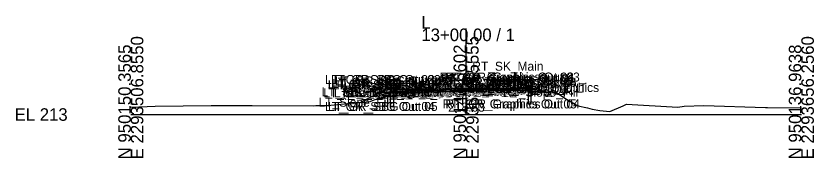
# Model space of a CAD drawing. Extents: x -26 to 7053, y -10 to 7035.
# Drawn here: x -25.7 to 152.8, y 1990.3 to 2022 of the extents above; entities that cross this region are included whole.
import ezdxf

# ---------------------------------------------------------------- set-up
doc = ezdxf.new("R2010")
doc.units = 0
for name, color, linetype in [('Default', 7, 'Continuous'), ('Exist Cross Section Cell', 7, 'Continuous'), ('Exist XS Center Line Elevation Label', 7, 'Continuous'), ('Exist XS Ground Line', 7, 'Continuous'), ('Prop CMT Conc Surface', 7, 'Continuous'), ('Prop CMT Concrete Structures', 7, 'Continuous'), ('Prop CMT Guardrail Graphics', 7, 'Continuous'), ('Prop CMT Guardrail SBG', 7, 'Continuous'), ('Prop CMT Pvmt Course 1', 7, 'Continuous'), ('Prop CMT Pvmt Course 2', 7, 'Continuous'), ('Prop CMT Pvmt Course SBG', 7, 'Continuous'), ('Prop CMT Pvmt Surface', 7, 'Continuous'), ('Prop CMT Pvmt Surface Overlay', 7, 'Continuous'), ('Prop CMT Pvmt Surface Shoulder', 7, 'Continuous'), ('Prop CMT Shld Paved Course 1', 7, 'Continuous'), ('Prop CMT Shld Paved Course 2', 7, 'Continuous'), ('Prop CMT Slope Grass', 7, 'Continuous'), ('Prop CMT Subgrade Earthwork', 7, 'Continuous'), ('Prop XS EOT Tick Mark', 7, 'Continuous'), ('Prop XS SE Text', 7, 'Continuous'), ('Prop XS Side Slope Text', 7, 'Continuous')]:
    doc.layers.add(name, color=color, linetype=linetype)

msp = doc.modelspace()

# ---------------------------------------------------------------- linework, layer by layer
at = {"layer": 'Exist Cross Section Cell'}
for p, q in [((75, 2000), (75, 2019.17)), ((0, 2000), (75, 2000)), ((75, 2000), (150, 2000))]:
    msp.add_line(p, q, dxfattribs=at)
at = {"layer": 'Exist XS Ground Line'}
for p, q in [((63.41, 2004.79), (66.65, 2005.24)), ((66.65, 2005.24), (67.11, 2005.31)), ((67.11, 2005.31), (67.58, 2005.32)), ((67.58, 2005.32), (75.03, 2005.63)), ((75.03, 2005.63), (82.28, 2005.69)), ((82.28, 2005.69), (83.65, 2005.7)), ((83.65, 2005.7), (85.36, 2005.56)), ((85.36, 2005.56), (95.43, 2004.79)), ((54.05, 2003.12), (54.9, 2003.41)), ((54.9, 2003.41), (56.91, 2003.91)), ((56.91, 2003.91), (63.41, 2004.79)), ((95.43, 2004.79), (97.12, 2003.62)), ((97.12, 2003.62), (100, 2001.97)), ((0, 2001.64), (5.42, 2001.85)), ((5.42, 2001.85), (17.98, 2002.01)), ((17.98, 2002.01), (20.9, 2001.99)), ((20.9, 2001.99), (27.15, 2002)), ((27.15, 2002), (40.89, 2001.96)), ((40.89, 2001.96), (41.42, 2002.03)), ((41.42, 2002.03), (43.98, 2002.04)), ((43.98, 2002.04), (50.01, 2002.64)), ((50.01, 2002.64), (53.56, 2002.89)), ((53.56, 2002.89), (54.05, 2003.12)), ((100, 2001.97), (102.17, 2001.49)), ((102.17, 2001.49), (103.24, 2001.19)), ((107.17, 2000.66), (110.15, 2001.96)), ((110.15, 2001.96), (110.87, 2002.28)), ((110.87, 2002.28), (122.35, 2001.67)), ((122.35, 2001.67), (123.79, 2001.84)), ((123.79, 2001.84), (128.22, 2002)), ((128.22, 2002), (141.98, 2001.57)), ((141.98, 2001.57), (142.43, 2001.58)), ((142.43, 2001.58), (150, 2001.51)), ((103.24, 2001.19), (104.94, 2000.92)), ((104.94, 2000.92), (107.17, 2000.66))]:
    msp.add_line(p, q, dxfattribs=at)
at = {"layer": 'Prop CMT Conc Surface'}
msp.add_lwpolyline([(62.03, 2005.51), (59.7, 2005.42), (59.03, 2005.76)], dxfattribs=at)
at = {"layer": 'Prop CMT Concrete Structures'}
for points in [[(62.03, 2005.51), (59.7, 2005.42), (59.03, 2005.76)], [(59.03, 2005.76), (59.03, 2005.09)], [(59.03, 2005.09), (62.03, 2005.09)], [(62.03, 2005.09), (62.03, 2005.51)]]:
    msp.add_lwpolyline(points, dxfattribs=at)
at = {"layer": 'Prop CMT Guardrail Graphics'}
for points in [[(89.55, 2008.36), (88.22, 2008.36), (87.95, 2008.07)], [(87.95, 2008.07), (88.22, 2007.78)], [(88.22, 2007.78), (87.95, 2007.48)], [(87.95, 2007.48), (88.22, 2007.19), (88.89, 2007.19)], [(88.89, 2007.19), (88.89, 2002.36)], [(89.55, 2002.36), (89.55, 2008.36)], [(88.89, 2002.36), (89.55, 2002.36)]]:
    msp.add_lwpolyline(points, dxfattribs=at)
at = {"layer": 'Prop CMT Guardrail SBG'}
for points in [[(58.09, 2001.8), (58.09, 2007.8)], [(58.09, 2007.8), (59.43, 2007.8), (59.7, 2007.5)], [(59.7, 2006.92), (59.43, 2006.63), (58.76, 2006.63)], [(59.7, 2007.5), (59.43, 2007.21)], [(59.43, 2007.21), (59.7, 2006.92)], [(58.76, 2006.63), (58.76, 2001.8)], [(58.76, 2001.8), (58.09, 2001.8)]]:
    msp.add_lwpolyline(points, dxfattribs=at)
at = {"layer": 'Prop CMT Pvmt Course 1'}
for points in [[(75, 2005.77), (65, 2005.57)], [(65, 2005.57), (65, 2005.32)], [(65, 2005.32), (75, 2005.52)], [(75, 2005.77), (85, 2005.97)], [(75, 2005.64), (75, 2005.77)], [(75, 2005.64), (75, 2005.77)], [(85, 2005.72), (75, 2005.52)], [(75, 2005.52), (75, 2005.64), (75, 2005.64)], [(75, 2005.52), (75, 2005.64), (75, 2005.64)], [(85, 2005.97), (85, 2005.72)]]:
    msp.add_lwpolyline(points, dxfattribs=at)
at = {"layer": 'Prop CMT Pvmt Course 2'}
for points in [[(75, 2005.52), (65, 2005.32)], [(65, 2005.32), (65, 2004.98)], [(65, 2004.98), (75, 2005.18)], [(75, 2005.52), (85, 2005.72)], [(75, 2005.18), (75, 2005.52)], [(75, 2005.18), (75, 2005.52)], [(85, 2005.38), (75, 2005.18)], [(85, 2005.72), (85, 2005.38)]]:
    msp.add_lwpolyline(points, dxfattribs=at)
at = {"layer": 'Prop CMT Pvmt Course SBG'}
for points in [[(62.03, 2005.09), (59.03, 2005.09), (58.53, 2005.09), (58.28, 2004.84)], [(62.03, 2004.84), (62.03, 2005.09)], [(58.28, 2004.84), (62.03, 2004.84)]]:
    msp.add_lwpolyline(points, dxfattribs=at)
at = {"layer": 'Prop CMT Pvmt Surface'}
for points in [[(75, 2005.77), (65, 2005.57)], [(75, 2005.77), (85, 2005.97)]]:
    msp.add_lwpolyline(points, dxfattribs=at)
at = {"layer": 'Prop CMT Pvmt Surface Overlay'}
for points in [[(75, 2005.77), (65, 2005.57)], [(75, 2005.77), (85, 2005.97)]]:
    msp.add_lwpolyline(points, dxfattribs=at)
at = {"layer": 'Prop CMT Pvmt Surface Shoulder'}
for points in [[(65, 2005.57), (62.03, 2005.51)], [(85, 2005.97), (87.93, 2006.03)]]:
    msp.add_lwpolyline(points, dxfattribs=at)
at = {"layer": 'Prop CMT Shld Paved Course 1'}
for points in [[(65, 2005.57), (62.03, 2005.51)], [(62.03, 2005.51), (62.03, 2005.26)], [(62.03, 2005.26), (65, 2005.32)], [(65, 2005.32), (65, 2005.57)], [(85, 2005.97), (87.93, 2006.03), (88.18, 2005.78)], [(85, 2005.72), (85, 2005.97)], [(88.18, 2005.78), (85, 2005.72)]]:
    msp.add_lwpolyline(points, dxfattribs=at)
at = {"layer": 'Prop CMT Shld Paved Course 2'}
for points in [[(65, 2005.32), (62.03, 2005.26)], [(62.03, 2005.26), (62.03, 2005.09), (62.03, 2004.93)], [(62.03, 2004.93), (65, 2004.98)], [(65, 2004.98), (65, 2005.32)], [(85, 2005.72), (88.18, 2005.78), (88.68, 2005.79), (89, 2005.46)], [(85, 2005.38), (85, 2005.72)], [(89, 2005.46), (85, 2005.38)]]:
    msp.add_lwpolyline(points, dxfattribs=at)
at = {"layer": 'Prop CMT Slope Grass'}
for points in [[(59.03, 2005.76), (58.28, 2006.14), (51.48, 2002.74)], [(87.93, 2006.03), (87.95, 2006.03)], [(87.95, 2006.03), (90.95, 2005.91)], [(90.95, 2005.91), (92.78, 2004.99)]]:
    msp.add_lwpolyline(points, dxfattribs=at)
at = {"layer": 'Prop CMT Subgrade Earthwork'}
for points in [[(65, 2004.98), (62.03, 2004.93)], [(62.03, 2004.93), (62.03, 2004.84)], [(75, 2005.18), (65, 2004.98)], [(75, 2005.18), (85, 2005.38)], [(85, 2005.38), (89, 2005.46)], [(89, 2005.46), (89.5, 2005.96)], [(62.03, 2004.84), (58.28, 2004.84), (55.68, 2004.84)]]:
    msp.add_lwpolyline(points, dxfattribs=at)
at = {"layer": 'Prop XS EOT Tick Mark'}
for p, q in [((65, 2005.57), (65, 2007.47)), ((85, 2005.97), (85, 2007.87))]:
    msp.add_line(p, q, dxfattribs=at)

# ---------------------------------------------------------------- texts
at = {"layer": 'Default'}
for s, height, p in [('RT_SK_Main', 2, (76.4, 2009.77)), ('LT_GR_SBG Out 03', 2, (43.45, 2006.8)), ('LT_GR_SBG Out 02', 2, (44.78, 2006.8)), ('LT_GR_SBG Out 01', 2, (45.62, 2006.5)), ('RT_GR_Graphics Out 08', 2, (68.8, 2006.48)), ('RT_GR_Graphics Out 02', 2, (69.07, 2007.36)), ('RT_GR_Graphics Out 09', 2, (69.07, 2006.78)), ('RT_GR_Graphics Out 01', 2, (69.37, 2007.07)), ('RT_GR_Graphics Out 03', 2, (70.4, 2007.36)), ('LT_GR_SBG Out 06', 2, (44.07, 2005.63)), ('LT_GR_SBG Out 09', 2, (44.78, 2006.21)), ('LT_GR_SBG Out 07', 2, (44.78, 2005.63)), ('LT_GR_SBG Out 08', 2, (45.05, 2005.92)), ('LT_CG_Top_BOC', 2, (47.31, 2004.76)), ('LT_GS_OS_CTL', 2, (47.65, 2005.14)), ('LT_TM_OEOT', 2, (57.94, 2005.61)), ('RT_GS_OS_GR_Face_Graphics', 2, (65.36, 2005.03)), ('RT_GR_Graphics Out 07', 2, (69.07, 2006.19)), ('PV1_PGL', 2, (69.47, 2004.77)), ('RT_GR_Graphics Out 06', 2, (69.69, 2006.19)), ('RT_Sub_Trench_Out_DLT', 2, (70.02, 2004.96)), ('RT_TM_OEOT', 2, (73.9, 2005.93)), ('RT_PS2_Shelf_Out', 2, (74.61, 2004.79)), ('RT_PV2_OEOT', 2, (75.13, 2004.72)), ('RT_PV1_OEOT', 2, (75.69, 2004.97)), ('RT_PS2_OEOP', 2, (78.37, 2004.78)), ('RT_PS1_OEOP', 2, (78.69, 2005.03)), ('RT_GS_OS_CTL', 2, (80.27, 2004.91)), ('LT_SBG_C1 Shelf Out', 2, (42.67, 2004.09)), ('LT_Sub_OSS_DLT', 2, (43.08, 2003.84)), ('LT_Sub_SBG Out', 2, (45.46, 2003.84)), ('LT_CG_Bot_BOC', 2, (47.35, 2004.09)), ('LT_CG_Top_Gut', 2, (47.93, 2004.42)), ('LT_Sub_OEOP_SBG', 2, (48.49, 2003.84)), ('LT_CG_Bot_IE', 2, (51.94, 2004.09)), ('LT_Sub_OEOP', 2, (52.14, 2003.93)), ('LT_PS2_OEOP', 2, (52.27, 2004.26)), ('LT_PS1_OEOP', 2, (52.83, 2004.51)), ('LT_Sub_OEOT', 2, (55.08, 2003.98)), ('LT_PV2_OEOT', 2, (55.17, 2004.32)), ('LT_PV1_OEOT', 2, (55.74, 2004.57)), ('RT_PV1_OEEOP_W', 2, (62.94, 2004.64)), ('LT_PV1_OEEOP_W', 2, (62.98, 2004.64)), ('RT_Sub_OEEOP', 2, (64.17, 2004.18)), ('LT_Sub_OEEOP', 2, (64.21, 2004.18)), ('RT_PV2_OEEOP', 2, (64.26, 2004.52)), ('LT_PV2_OEEOP', 2, (64.31, 2004.52)), ('PV1_PGL_W', 2, (67.58, 2004.64)), ('RT_Sub_Trench_Out', 2, (73.16, 2004.46)), ('RT_Sub_OEOT', 2, (75.03, 2004.38)), ('RT_Slope_Fill', 2, (83.25, 2003.99)), ('LT_Slope_Fill', 2, (42, 2001.74)), ('RT_GR_Graphics Out 05', 2, (69.74, 2001.36)), ('RT_GR_Graphics Out 04', 2, (70.4, 2001.36)), ('LT_GR_SBG Out 04', 2, (43.45, 2000.8)), ('LT_GR_SBG Out 05', 2, (44.11, 2000.8)), ('-', 0.0001, (0, 2000))]:
    msp.add_text(s, height=height, dxfattribs=at).set_placement(p)
at = {"layer": 'Exist Cross Section Cell'}
for s, p in [('L', (65, 2019.17)), ('13+00.00 / 1', (65, 2016.37)), ('EL 213', (-26, 1998.6))]:
    msp.add_text(s, height=2.8, dxfattribs=at).set_placement(p)
for s, p in [('E 2293506.8550', (2.8, 1990)), ('E 2293581.5555', (77.8, 1990)), ('E 2293656.2560', (152.8, 1990)), ('N 950150.3565', (0, 1990)), ('N 950143.6602', (75, 1990)), ('N 950136.9638', (150, 1990))]:
    msp.add_text(s, height=2.8, rotation=90, dxfattribs=at).set_placement(p)
at = {"layer": 'Exist XS Center Line Elevation Label'}
msp.add_text('218.63', height=2, dxfattribs=at).set_placement((70.99, 2000.63))
at = {"layer": 'Prop XS SE Text'}
for p in [(67.36, 2006.62), (77.36, 2006.82)]:
    msp.add_text('0.020', height=1.5, rotation=1.1458, dxfattribs=at).set_placement(p)
at = {"layer": 'Prop XS Side Slope Text'}
for rotation, p in [(26.5651, (53.48, 2004.58)), (333.4349, (91.14, 2006.65))]:
    msp.add_text('2:1', height=1.5, rotation=rotation, dxfattribs=at).set_placement(p)

doc.saveas('drawing.dxf')
